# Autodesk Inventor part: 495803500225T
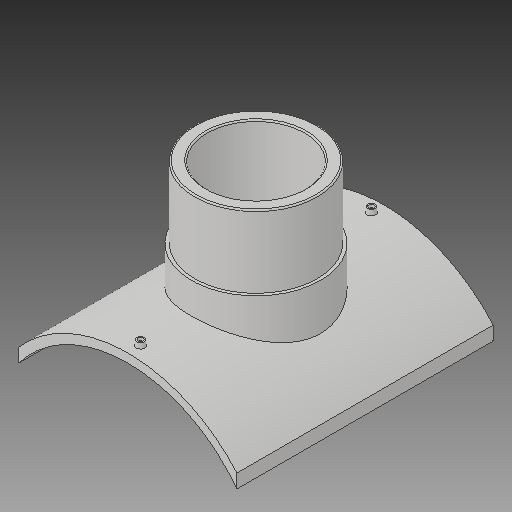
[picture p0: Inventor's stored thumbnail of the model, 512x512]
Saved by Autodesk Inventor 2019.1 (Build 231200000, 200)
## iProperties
Created: 2017-10
Part Number: 495803500225T
Material: Generic
Description: PLASSON BRANCH SADDLE  500x225
Document SubType Name: Modeling
Designer: KIM
Mass: 2754.05 g
Surface Area: 3037.44 cm^2
Volume: 2754.05 cm^3
Density: 1 g/cm^3
Appearance: Default
Author: KIM
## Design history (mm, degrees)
derived "495803.ipt"
feature "Solid1::495803.ipt"
tag "TaggingFeature1"
body "Solid1"
other parameters: "d1" = 16, "d4" = 0, "d12" = 275.6, "d13" = 14, "d14" = 211.5, "d16" = 5 deg, "d18" = 4, "d19" = 14, "d20" = 0, "d21" = 3, "d22" = 0, "d23" = 455, "d24" = 236.25, "d25" = 16, "d28" = 0, "d29" = 9.6, "d31" = 0, "d32" = 94.5, "d33" = 0, "d34" = 5, "d36" = 225, "d37" = 132.3, "d38" = 0, "d39" = 2.5, "d_1" = 225, "H_" = 189, "x_" = 16, "D_" = 16
